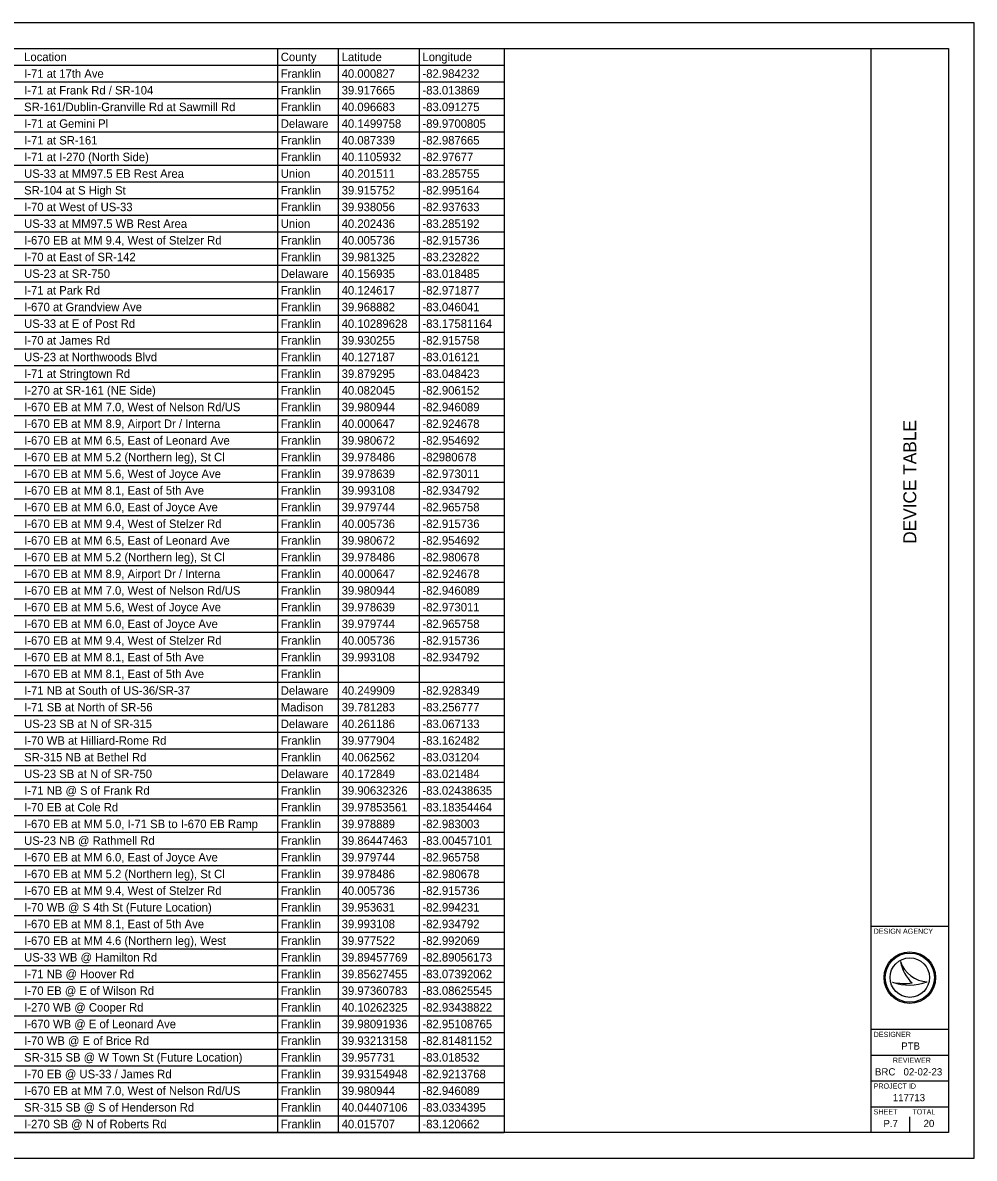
# Model space of a CAD drawing. Extents: x 0 to 34, y 0 to 22.
# Drawn here: x 15.56 to 34, y 0 to 22 of the extents above; entities that cross this region are included whole.
import ezdxf

# ---------------------------------------------------------------- set-up
doc = ezdxf.new("R2010")
doc.units = 0
for name, color, linetype in [('SH_Border', 7, 'Continuous'), ('SH_Cut_Line', 7, 'Continuous'), ('SH_Data', 7, 'Continuous'), ('SH_Text', 7, 'Continuous')]:
    doc.layers.add(name, color=color, linetype=linetype)

msp = doc.modelspace()

# ---------------------------------------------------------------- linework, layer by layer
at = {"layer": 'SH_Border'}
for p, q in [((32, 0.5), (32, 21.5)), ((32, 4.5), (33.5, 4.5)), ((32, 2.5), (33.5, 2.5)), ((32, 2), (33.5, 2)), ((32, 1.5), (33.5, 1.5)), ((32, 1), (33.5, 1))]:
    msp.add_line(p, q, dxfattribs=at)
msp.add_lwpolyline([(1.5, 21.5), (33.5, 21.5), (33.5, 0.5), (1.5, 0.5)], close=True, dxfattribs=at)
at = {"layer": 'SH_Cut_Line'}
msp.add_lwpolyline([(0, 0), (34, 0), (34, 22), (0, 22)], close=True, dxfattribs=at)
at = {"layer": 'SH_Data'}
for p, q in [((32.567, 3.81), (32.567, 3.81)), ((32.417, 3.41), (32.417, 3.41)), ((32.75, 3.5), (32.75, 3.5)), ((33.087, 3.419), (33.087, 3.419)), ((32.375, 0.675), (32.375, 0.675)), ((32.75, 0.5), (32.75, 0.8))]:
    msp.add_line(p, q, dxfattribs=at)
for radius in [0.5, 0.477, 0.477, 0.382]:
    msp.add_circle((32.75, 3.5), radius, dxfattribs=at)
for centre, radius, start, end in [((33.116, 3.998), 0.58, 198.9257, 198.9319), ((33.347, 3.97), 0.796, 191.6379, 191.6421), ((33.116, 3.998), 0.58, 198.9319, 267.1657), ((33.347, 3.97), 0.796, 191.6421, 226.0947), ((32.739, 4.37), 1.013, 251.4576, 290.0832), ((32.648, 4.654), 1.266, 259.4964, 259.4995), ((32.739, 4.37), 1.013, 251.4527, 251.4576), ((32.648, 4.654), 1.266, 259.4995, 276.6672)]:
    msp.add_arc(centre, radius, start, end, dxfattribs=at)
at = {"layer": 'SH_Text'}
for p, q in [((1.5, 21.5), (24.888, 21.5)), ((20.495, 21.5), (20.495, 0.502)), ((21.674, 21.5), (21.674, 0.502)), ((23.241, 21.5), (23.241, 0.502)), ((24.888, 21.5), (24.888, 0.502)), ((1.5, 21.177), (24.888, 21.177)), ((1.5, 20.854), (24.888, 20.854)), ((1.5, 20.531), (24.888, 20.531)), ((1.5, 20.208), (24.888, 20.208)), ((1.5, 19.884), (24.888, 19.884)), ((1.5, 19.561), (24.888, 19.561)), ((1.5, 19.238), (24.888, 19.238)), ((1.5, 18.915), (24.888, 18.915)), ((1.5, 18.592), (24.888, 18.592)), ((1.5, 18.269), (24.888, 18.269)), ((1.5, 17.946), (24.888, 17.946)), ((1.5, 17.623), (24.888, 17.623)), ((1.5, 17.3), (24.888, 17.3)), ((1.5, 16.977), (24.888, 16.977)), ((1.5, 16.654), (24.888, 16.654)), ((1.5, 16.331), (24.888, 16.331)), ((1.5, 16.008), (24.888, 16.008)), ((1.5, 15.685), (24.888, 15.685)), ((1.5, 15.362), (24.888, 15.362)), ((1.5, 15.039), (24.888, 15.039)), ((1.5, 14.716), (24.888, 14.716)), ((1.5, 14.393), (24.888, 14.393)), ((1.5, 14.07), (24.888, 14.07)), ((1.5, 13.747), (24.888, 13.747)), ((1.5, 13.424), (24.888, 13.424)), ((1.5, 13.101), (24.888, 13.101)), ((1.5, 12.778), (24.888, 12.778)), ((1.5, 12.455), (24.888, 12.455)), ((1.5, 12.131), (24.888, 12.131)), ((1.5, 11.808), (24.888, 11.808)), ((1.5, 11.485), (24.888, 11.485)), ((1.5, 11.162), (24.888, 11.162)), ((1.5, 10.839), (24.888, 10.839)), ((1.5, 10.516), (24.888, 10.516)), ((1.5, 10.193), (24.888, 10.193)), ((1.5, 9.87), (24.888, 9.87)), ((1.5, 9.547), (24.888, 9.547)), ((1.5, 9.224), (24.888, 9.224)), ((1.5, 8.901), (24.888, 8.901)), ((1.5, 8.578), (24.888, 8.578)), ((1.5, 8.255), (24.888, 8.255)), ((1.5, 7.932), (24.888, 7.932)), ((1.5, 7.609), (24.888, 7.609)), ((1.5, 7.286), (24.888, 7.286)), ((1.5, 6.963), (24.888, 6.963)), ((1.5, 6.64), (24.888, 6.64)), ((1.5, 6.317), (24.888, 6.317)), ((1.5, 5.994), (24.888, 5.994)), ((1.5, 5.671), (24.888, 5.671)), ((1.5, 5.348), (24.888, 5.348)), ((1.5, 5.025), (24.888, 5.025)), ((1.5, 4.701), (24.888, 4.701)), ((1.5, 4.378), (24.888, 4.378)), ((1.5, 4.055), (24.888, 4.055)), ((1.5, 3.732), (24.888, 3.732)), ((1.5, 3.409), (24.888, 3.409)), ((1.5, 3.086), (24.888, 3.086)), ((1.5, 2.763), (24.888, 2.763)), ((1.5, 2.44), (24.888, 2.44)), ((1.5, 2.117), (24.888, 2.117)), ((1.5, 1.794), (24.888, 1.794)), ((1.5, 1.471), (24.888, 1.471)), ((1.5, 1.148), (24.888, 1.148)), ((1.5, 0.825), (24.888, 0.825)), ((1.5, 0.502), (24.888, 0.502))]:
    msp.add_line(p, q, dxfattribs=at)

# ---------------------------------------------------------------- texts
at = {"layer": 'SH_Data'}
msp.add_text('DEVICE TABLE', height=0.25, rotation=90, dxfattribs=at).set_placement((32.875, 11.905))
for s, height, p in [('DESIGN AGENCY', 0.1, (32.05, 4.35)), ('DESIGNER', 0.1, (32.05, 2.35)), ('PTB', 0.14, (32.584, 2.105)), ('REVIEWER', 0.1, (32.422, 1.85)), ('BRC', 0.14, (32.075, 1.605)), ('02-02-23', 0.14, (32.629, 1.605)), ('PROJECT ID', 0.1, (32.05, 1.35)), ('117713', 0.14, (32.421, 1.105)), ('SHEET', 0.1, (32.05, 0.85)), ('TOTAL', 0.1, (32.8, 0.85)), ('P.7', 0.14, (32.239, 0.605)), ('20', 0.14, (33.017, 0.605))]:
    msp.add_text(s, height=height, dxfattribs=at).set_placement(p)
at = {"layer": 'SH_Text'}
for s, height, p in [('Location', 0.1635, (15.585, 21.256)), ('County', 0.1635, (20.559, 21.256)), ('Latitude', 0.1635, (21.739, 21.256)), ('Longitude', 0.1635, (23.305, 21.256)), ('I-71 at 17th Ave', 0.16346, (15.585, 20.933)), ('Franklin', 0.1635, (20.559, 20.933)), ('40.000827', 0.1635, (21.739, 20.933)), ('-82.984232', 0.1635, (23.305, 20.933)), ('I-71 at Frank Rd / SR-104', 0.16346, (15.585, 20.61)), ('Franklin', 0.1635, (20.559, 20.61)), ('39.917665', 0.1635, (21.739, 20.61)), ('-83.013869', 0.1635, (23.305, 20.61)), ('SR-161/Dublin-Granville Rd at Sawmill Rd', 0.16346, (15.585, 20.287)), ('Franklin', 0.1635, (20.559, 20.287)), ('40.096683', 0.1635, (21.739, 20.287)), ('-83.091275', 0.1635, (23.305, 20.287)), ('I-71 at Gemini Pl', 0.16346, (15.585, 19.964)), ('Delaware', 0.1635, (20.559, 19.964)), ('40.1499758', 0.1635, (21.739, 19.964)), ('-89.9700805', 0.16346, (23.305, 19.964)), ('I-71 at SR-161', 0.16346, (15.585, 19.641)), ('Franklin', 0.1635, (20.559, 19.641)), ('40.087339', 0.1635, (21.739, 19.641)), ('-82.987665', 0.1635, (23.305, 19.641)), ('I-71 at I-270 (North Side)', 0.16346, (15.585, 19.318)), ('Franklin', 0.1635, (20.559, 19.318)), ('40.1105932', 0.1635, (21.739, 19.318)), ('-82.97677', 0.1635, (23.305, 19.318)), ('US-33 at MM97.5 EB Rest Area', 0.16346, (15.585, 18.995)), ('Union', 0.1635, (20.559, 18.995)), ('40.201511', 0.1635, (21.739, 18.995)), ('-83.285755', 0.1635, (23.305, 18.995)), ('SR-104 at S High St', 0.16346, (15.585, 18.672)), ('Franklin', 0.1635, (20.559, 18.672)), ('39.915752', 0.1635, (21.739, 18.672)), ('-82.995164', 0.1635, (23.305, 18.672)), ('I-70 at West of US-33', 0.16346, (15.585, 18.349)), ('Franklin', 0.1635, (20.559, 18.349)), ('39.938056', 0.1635, (21.739, 18.349)), ('-82.937633', 0.1635, (23.305, 18.349)), ('US-33 at MM97.5 WB Rest Area', 0.16346, (15.585, 18.026)), ('Union', 0.1635, (20.559, 18.026)), ('40.202436', 0.1635, (21.739, 18.026)), ('-83.285192', 0.1635, (23.305, 18.026)), ('I-670 EB at MM 9.4, West of Stelzer Rd', 0.16346, (15.585, 17.703)), ('Franklin', 0.1635, (20.559, 17.703)), ('40.005736', 0.1635, (21.739, 17.703)), ('-82.915736', 0.1635, (23.305, 17.703)), ('I-70 at East of SR-142', 0.16346, (15.585, 17.38)), ('Franklin', 0.1635, (20.559, 17.38)), ('39.981325', 0.1635, (21.739, 17.38)), ('-83.232822', 0.1635, (23.305, 17.38)), ('US-23 at SR-750', 0.16346, (15.585, 17.057)), ('Delaware', 0.1635, (20.559, 17.057)), ('40.156935', 0.1635, (21.739, 17.057)), ('-83.018485', 0.1635, (23.305, 17.057)), ('I-71 at Park Rd', 0.16346, (15.585, 16.734)), ('Franklin', 0.1635, (20.559, 16.734)), ('40.124617', 0.1635, (21.739, 16.734)), ('-82.971877', 0.1635, (23.305, 16.734)), ('I-670 at Grandview Ave', 0.16346, (15.585, 16.411)), ('Franklin', 0.1635, (20.559, 16.411)), ('39.968882', 0.1635, (21.739, 16.411)), ('-83.046041', 0.1635, (23.305, 16.411)), ('US-33 at E of Post Rd', 0.16346, (15.585, 16.088)), ('Franklin', 0.1635, (20.559, 16.088)), ('40.10289628', 0.16346, (21.739, 16.088)), ('-83.17581164', 0.16346, (23.305, 16.088)), ('I-70 at James Rd', 0.16346, (15.585, 15.765)), ('Franklin', 0.1635, (20.559, 15.765)), ('39.930255', 0.1635, (21.739, 15.765)), ('-82.915758', 0.1635, (23.305, 15.765)), ('US-23 at Northwoods Blvd', 0.16346, (15.585, 15.442)), ('Franklin', 0.1635, (20.559, 15.442)), ('40.127187', 0.1635, (21.739, 15.442)), ('-83.016121', 0.1635, (23.305, 15.442)), ('I-71 at Stringtown Rd', 0.16346, (15.585, 15.119)), ('Franklin', 0.1635, (20.559, 15.119)), ('39.879295', 0.1635, (21.739, 15.119)), ('-83.048423', 0.1635, (23.305, 15.119)), ('I-270 at SR-161 (NE Side)', 0.16346, (15.585, 14.796)), ('Franklin', 0.1635, (20.559, 14.796)), ('40.082045', 0.1635, (21.739, 14.796)), ('-82.906152', 0.1635, (23.305, 14.796)), ('I-670 EB at MM 7.0, West of Nelson Rd/US', 0.16346, (15.585, 14.473)), ('Franklin', 0.1635, (20.559, 14.473)), ('39.980944', 0.1635, (21.739, 14.473)), ('-82.946089', 0.1635, (23.305, 14.473)), ('I-670 EB at MM 8.9, Airport Dr / Interna', 0.16346, (15.585, 14.15)), ('Franklin', 0.1635, (20.559, 14.15)), ('40.000647', 0.1635, (21.739, 14.15)), ('-82.924678', 0.1635, (23.305, 14.15)), ('I-670 EB at MM 6.5, East of Leonard Ave', 0.16346, (15.585, 13.826)), ('Franklin', 0.1635, (20.559, 13.826)), ('39.980672', 0.1635, (21.739, 13.826)), ('-82.954692', 0.1635, (23.305, 13.826)), ('I-670 EB at MM 5.2 (Northern leg), St Cl', 0.16346, (15.585, 13.503)), ('Franklin', 0.1635, (20.559, 13.503)), ('39.978486', 0.1635, (21.739, 13.503)), ('-82980678', 0.1635, (23.305, 13.503)), ('I-670 EB at MM 5.6, West of Joyce Ave', 0.16346, (15.585, 13.18)), ('Franklin', 0.1635, (20.559, 13.18)), ('39.978639', 0.1635, (21.739, 13.18)), ('-82.973011', 0.1635, (23.305, 13.18)), ('I-670 EB at MM 8.1, East of 5th Ave', 0.16346, (15.585, 12.857)), ('Franklin', 0.1635, (20.559, 12.857)), ('39.993108', 0.1635, (21.739, 12.857)), ('-82.934792', 0.1635, (23.305, 12.857)), ('I-670 EB at MM 6.0, East of Joyce Ave', 0.16346, (15.585, 12.534)), ('Franklin', 0.1635, (20.559, 12.534)), ('39.979744', 0.1635, (21.739, 12.534)), ('-82.965758', 0.1635, (23.305, 12.534)), ('I-670 EB at MM 9.4, West of Stelzer Rd', 0.16346, (15.585, 12.211)), ('Franklin', 0.1635, (20.559, 12.211)), ('40.005736', 0.1635, (21.739, 12.211)), ('-82.915736', 0.1635, (23.305, 12.211)), ('I-670 EB at MM 6.5, East of Leonard Ave', 0.16346, (15.585, 11.888)), ('Franklin', 0.1635, (20.559, 11.888)), ('39.980672', 0.1635, (21.739, 11.888)), ('-82.954692', 0.1635, (23.305, 11.888)), ('I-670 EB at MM 5.2 (Northern leg), St Cl', 0.16346, (15.585, 11.565)), ('Franklin', 0.1635, (20.559, 11.565)), ('39.978486', 0.1635, (21.739, 11.565)), ('-82.980678', 0.1635, (23.305, 11.565)), ('I-670 EB at MM 8.9, Airport Dr / Interna', 0.16346, (15.585, 11.242)), ('Franklin', 0.1635, (20.559, 11.242)), ('40.000647', 0.1635, (21.739, 11.242)), ('-82.924678', 0.1635, (23.305, 11.242)), ('I-670 EB at MM 7.0, West of Nelson Rd/US', 0.16346, (15.585, 10.919)), ('Franklin', 0.1635, (20.559, 10.919)), ('39.980944', 0.1635, (21.739, 10.919)), ('-82.946089', 0.1635, (23.305, 10.919)), ('I-670 EB at MM 5.6, West of Joyce Ave', 0.16346, (15.585, 10.596)), ('Franklin', 0.1635, (20.559, 10.596)), ('39.978639', 0.1635, (21.739, 10.596)), ('-82.973011', 0.1635, (23.305, 10.596)), ('I-670 EB at MM 6.0, East of Joyce Ave', 0.16346, (15.585, 10.273)), ('Franklin', 0.1635, (20.559, 10.273)), ('39.979744', 0.1635, (21.739, 10.273)), ('-82.965758', 0.1635, (23.305, 10.273)), ('I-670 EB at MM 9.4, West of Stelzer Rd', 0.16346, (15.585, 9.95)), ('Franklin', 0.1635, (20.559, 9.95)), ('40.005736', 0.1635, (21.739, 9.95)), ('-82.915736', 0.1635, (23.305, 9.95)), ('I-670 EB at MM 8.1, East of 5th Ave', 0.16346, (15.585, 9.627)), ('Franklin', 0.1635, (20.559, 9.627)), ('39.993108', 0.1635, (21.739, 9.627)), ('-82.934792', 0.1635, (23.305, 9.627)), ('I-670 EB at MM 8.1, East of 5th Ave', 0.16346, (15.585, 9.304)), ('Franklin', 0.1635, (20.559, 9.304)), ('I-71 NB at South of US-36/SR-37', 0.16346, (15.585, 8.981)), ('Delaware', 0.1635, (20.559, 8.981)), ('40.249909', 0.1635, (21.739, 8.981)), ('-82.928349', 0.1635, (23.305, 8.981)), ('I-71 SB at North of SR-56', 0.16346, (15.585, 8.658)), ('Madison', 0.1635, (20.559, 8.658)), ('39.781283', 0.1635, (21.739, 8.658)), ('-83.256777', 0.1635, (23.305, 8.658)), ('US-23 SB at N of SR-315', 0.16346, (15.585, 8.335)), ('Delaware', 0.1635, (20.559, 8.335)), ('40.261186', 0.1635, (21.739, 8.335)), ('-83.067133', 0.1635, (23.305, 8.335)), ('I-70 WB at Hilliard-Rome Rd', 0.16346, (15.585, 8.012)), ('Franklin', 0.1635, (20.559, 8.012)), ('39.977904', 0.1635, (21.739, 8.012)), ('-83.162482', 0.1635, (23.305, 8.012)), ('SR-315 NB at Bethel Rd', 0.16346, (15.585, 7.689)), ('Franklin', 0.1635, (20.559, 7.689)), ('40.062562', 0.1635, (21.739, 7.689)), ('-83.031204', 0.1635, (23.305, 7.689)), ('US-23 SB at N of SR-750', 0.16346, (15.585, 7.366)), ('Delaware', 0.1635, (20.559, 7.366)), ('40.172849', 0.1635, (21.739, 7.366)), ('-83.021484', 0.1635, (23.305, 7.366)), ('I-71 NB @ S of Frank Rd', 0.16346, (15.585, 7.043)), ('Franklin', 0.1635, (20.559, 7.043)), ('39.90632326', 0.16346, (21.739, 7.043)), ('-83.02438635', 0.16346, (23.305, 7.043)), ('I-70 EB at Cole Rd', 0.16346, (15.585, 6.72)), ('Franklin', 0.1635, (20.559, 6.72)), ('39.97853561', 0.16346, (21.739, 6.72)), ('-83.18354464', 0.16346, (23.305, 6.72)), ('I-670 EB at MM 5.0, I-71 SB to I-670 EB Ramp', 0.16346, (15.585, 6.396)), ('Franklin', 0.1635, (20.559, 6.396)), ('39.978889', 0.1635, (21.739, 6.396)), ('-82.983003', 0.1635, (23.305, 6.396)), ('US-23 NB @ Rathmell Rd', 0.16346, (15.585, 6.073)), ('Franklin', 0.1635, (20.559, 6.073)), ('39.86447463', 0.16346, (21.739, 6.073)), ('-83.00457101', 0.16346, (23.305, 6.073)), ('I-670 EB at MM 6.0, East of Joyce Ave', 0.16346, (15.585, 5.75)), ('Franklin', 0.1635, (20.559, 5.75)), ('39.979744', 0.1635, (21.739, 5.75)), ('-82.965758', 0.1635, (23.305, 5.75)), ('I-670 EB at MM 5.2 (Northern leg), St Cl', 0.16346, (15.585, 5.427)), ('Franklin', 0.1635, (20.559, 5.427)), ('39.978486', 0.1635, (21.739, 5.427)), ('-82.980678', 0.1635, (23.305, 5.427)), ('I-670 EB at MM 9.4, West of Stelzer Rd', 0.16346, (15.585, 5.104)), ('Franklin', 0.1635, (20.559, 5.104)), ('40.005736', 0.1635, (21.739, 5.104)), ('-82.915736', 0.1635, (23.305, 5.104)), ('I-70 WB @ S 4th St (Future Location)', 0.16346, (15.585, 4.781)), ('Franklin', 0.1635, (20.559, 4.781)), ('39.953631', 0.1635, (21.739, 4.781)), ('-82.994231', 0.1635, (23.305, 4.781)), ('I-670 EB at MM 8.1, East of 5th Ave', 0.16346, (15.585, 4.458)), ('Franklin', 0.1635, (20.559, 4.458)), ('39.993108', 0.1635, (21.739, 4.458)), ('-82.934792', 0.1635, (23.305, 4.458)), ('I-670 EB at MM 4.6 (Northern leg), West', 0.16346, (15.585, 4.135)), ('Franklin', 0.1635, (20.559, 4.135)), ('39.977522', 0.1635, (21.739, 4.135)), ('-82.992069', 0.1635, (23.305, 4.135)), ('US-33 WB @ Hamilton Rd', 0.16346, (15.585, 3.812)), ('Franklin', 0.1635, (20.559, 3.812)), ('39.89457769', 0.16346, (21.739, 3.812)), ('-82.89056173', 0.16346, (23.305, 3.812)), ('I-71 NB @ Hoover Rd', 0.16346, (15.585, 3.489)), ('Franklin', 0.1635, (20.559, 3.489)), ('39.85627455', 0.16346, (21.739, 3.489)), ('-83.07392062', 0.16346, (23.305, 3.489)), ('I-70 EB @ E of Wilson Rd', 0.16346, (15.585, 3.166)), ('Franklin', 0.1635, (20.559, 3.166)), ('39.97360783', 0.16346, (21.739, 3.166)), ('-83.08625545', 0.16346, (23.305, 3.166)), ('I-270 WB @ Cooper Rd', 0.16346, (15.585, 2.843)), ('Franklin', 0.1635, (20.559, 2.843)), ('40.10262325', 0.16346, (21.739, 2.843)), ('-82.93438822', 0.16346, (23.305, 2.843)), ('I-670 WB @ E of Leonard Ave', 0.16346, (15.585, 2.52)), ('Franklin', 0.1635, (20.559, 2.52)), ('39.98091936', 0.16346, (21.739, 2.52)), ('-82.95108765', 0.16346, (23.305, 2.52)), ('I-70 WB @ E of Brice Rd', 0.16346, (15.585, 2.197)), ('Franklin', 0.1635, (20.559, 2.197)), ('39.93213158', 0.16346, (21.739, 2.197)), ('-82.81481152', 0.16346, (23.305, 2.197)), ('SR-315 SB @ W Town St (Future Location)', 0.16346, (15.585, 1.874)), ('Franklin', 0.1635, (20.559, 1.874)), ('39.957731', 0.1635, (21.739, 1.874)), ('-83.018532', 0.1635, (23.305, 1.874)), ('I-70 EB @ US-33 / James Rd', 0.16346, (15.585, 1.551)), ('Franklin', 0.1635, (20.559, 1.551)), ('39.93154948', 0.16346, (21.739, 1.551)), ('-82.9213768', 0.16346, (23.305, 1.551)), ('I-670 EB at MM 7.0, West of Nelson Rd/US', 0.16346, (15.585, 1.228)), ('Franklin', 0.1635, (20.559, 1.228)), ('39.980944', 0.1635, (21.739, 1.228)), ('-82.946089', 0.1635, (23.305, 1.228)), ('SR-315 SB @ S of Henderson Rd', 0.16346, (15.585, 0.905)), ('Franklin', 0.1635, (20.559, 0.905)), ('40.04407106', 0.16346, (21.739, 0.905)), ('-83.0334395', 0.16346, (23.305, 0.905)), ('I-270 SB @ N of Roberts Rd', 0.16346, (15.585, 0.582)), ('Franklin', 0.1635, (20.559, 0.582)), ('40.015707', 0.1635, (21.739, 0.582)), ('-83.120662', 0.1635, (23.305, 0.582))]:
    msp.add_text(s, height=height, dxfattribs=at).set_placement(p)

doc.saveas('drawing.dxf')
